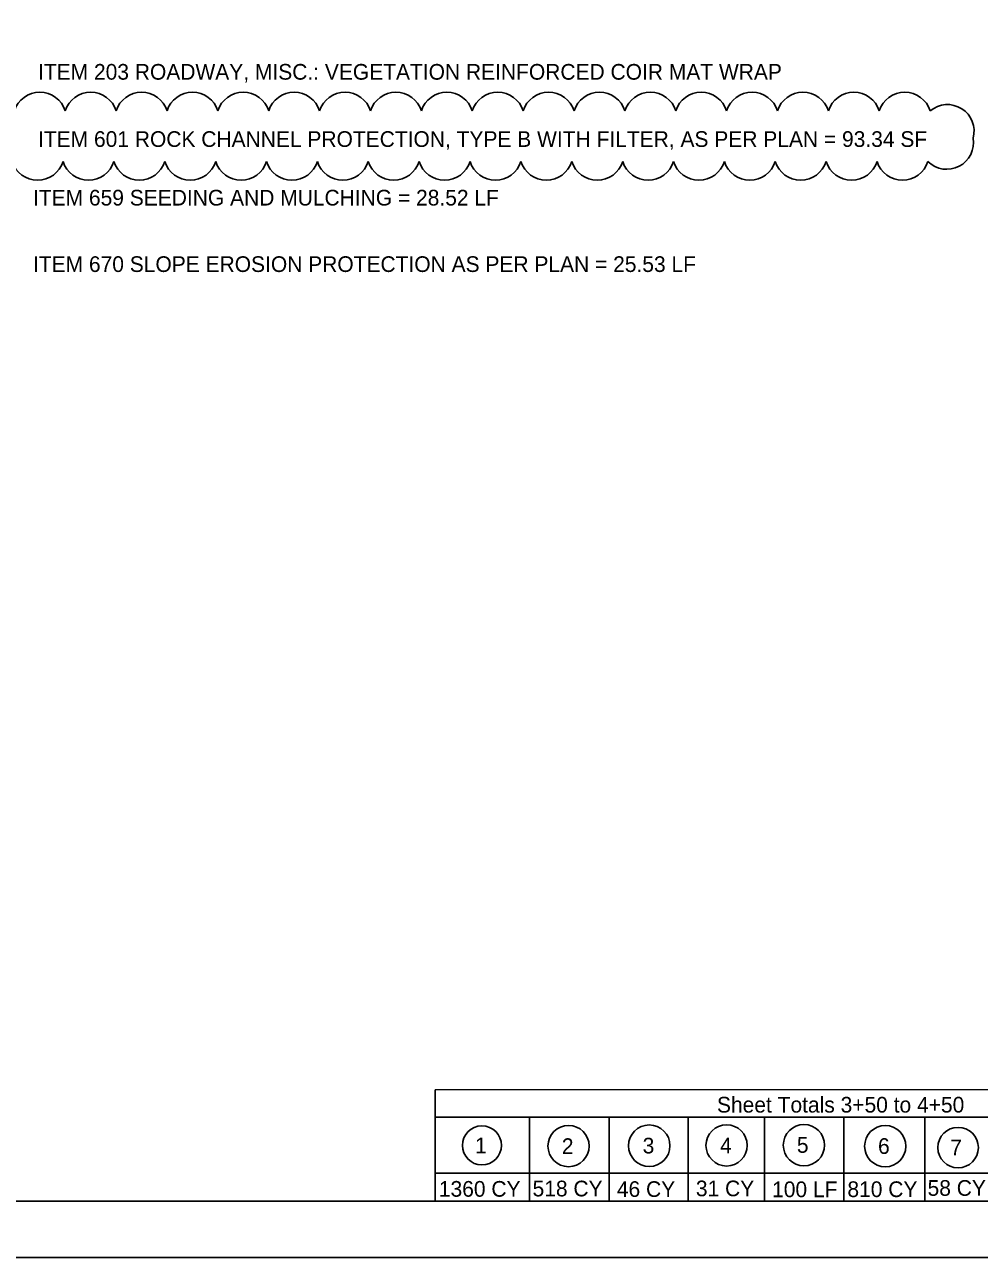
# Model space of a CAD drawing. Extents: x 0 to 34, y 0 to 22.
# Drawn here: x 21.21 to 29.73, y 0 to 11 of the extents above; entities that cross this region are included whole.
import ezdxf

# ---------------------------------------------------------------- set-up
doc = ezdxf.new("R2010")
doc.units = 0
for name, color, linetype in [('CS-ALGN-TEXT', 7, 'Continuous'), ('CS-ANNO', 7, 'Continuous'), ('CS-ANNO-MATC', 7, 'Continuous'), ('CS-ANNO-MATC-TEXT', 7, 'Continuous')]:
    doc.layers.add(name, color=color, linetype=linetype)

msp = doc.modelspace()

# ---------------------------------------------------------------- linework, layer by layer
at = {"layer": 'CS-ALGN-TEXT'}
for p, q in [((24.874, 1.496), (32, 1.5)), ((24.874, 0.496), (24.874, 1.496)), ((24.874, 1.25), (32, 1.25)), ((25.717, 0.496), (25.717, 1.246)), ((26.427, 0.496), (26.427, 1.246)), ((27.13, 0.496), (27.13, 1.246)), ((27.811, 0.496), (27.811, 1.246)), ((28.521, 0.496), (28.521, 1.246)), ((29.243, 0.496), (29.243, 1.246)), ((24.874, 0.75), (32, 0.75)), ((27.25, 0.5), (32, 0.5))]:
    msp.add_line(p, q, dxfattribs=at)
at = {"layer": 'CS-ANNO'}
msp.add_lwpolyline([(0, 0), (34, 0), (34, 22), (0, 22)], close=True, dxfattribs=at)
at = {"layer": 'CS-ANNO-MATC'}
msp.add_lwpolyline([(1.5, 21.5), (33.5, 21.5), (33.5, 0.5), (1.5, 0.5)], close=True, dxfattribs=at)
at = {"layer": 'CS-ANNO-MATC-TEXT'}
for centre, radius in [((25.291, 0.999), 0.174), ((26.064, 0.993), 0.184), ((26.784, 0.996), 0.185), ((27.474, 0.999), 0.184), ((28.164, 1.001), 0.184), ((28.889, 0.992), 0.184), ((29.539, 0.979), 0.181)]:
    msp.add_circle(centre, radius, dxfattribs=at)
for centre, start, end in [((21.347, 10.159), 17.5, 162.5), ((21.801, 10.159), 17.5, 162.5), ((22.255, 10.159), 17.5, 162.5), ((22.709, 10.159), 17.5, 162.5), ((23.162, 10.159), 17.5, 162.5), ((23.616, 10.159), 17.5, 162.5), ((24.07, 10.159), 17.5, 162.5), ((24.524, 10.159), 17.5, 162.5), ((24.978, 10.159), 17.5, 162.5), ((25.432, 10.159), 17.5, 162.5), ((25.886, 10.159), 17.5, 162.5), ((26.34, 10.159), 17.5, 162.5), ((26.794, 10.159), 17.5, 162.5), ((27.247, 10.159), 17.5, 162.5), ((27.701, 10.159), 17.5, 162.5), ((28.155, 10.159), 17.5, 162.5), ((28.609, 10.159), 17.5, 162.5), ((29.063, 10.159), 17.4564, 162.4564), ((29.444, 10.049), 345.1523, 130.1523), ((29.439, 9.947), 224.9312, 9.9312), ((21.327, 9.85), 197.5, 342.5), ((21.781, 9.85), 197.5, 342.5), ((22.235, 9.85), 197.5, 342.5), ((22.689, 9.85), 197.5, 342.5), ((23.143, 9.85), 197.5, 342.5), ((23.596, 9.85), 197.5, 342.5), ((24.05, 9.85), 197.5, 342.5), ((24.504, 9.85), 197.5, 342.5), ((24.958, 9.85), 197.5, 342.5), ((25.412, 9.85), 197.5, 342.5), ((25.866, 9.85), 197.5, 342.5), ((26.32, 9.85), 197.5, 342.5), ((26.774, 9.85), 197.5, 342.5), ((27.227, 9.85), 197.5, 342.5), ((27.681, 9.85), 197.5, 342.5), ((28.135, 9.85), 197.5, 342.5), ((28.589, 9.85), 197.5, 342.5), ((29.043, 9.85), 197.5, 342.5)]:
    msp.add_arc(centre, 0.238, start, end, dxfattribs=at)

# ---------------------------------------------------------------- texts
at = {"layer": 'CS-ALGN-TEXT'}
msp.add_text('Sheet Totals 3+50 to 4+50', height=0.14, dxfattribs=at).set_placement((27.388, 1.292))
at = {"layer": 'CS-ANNO-MATC-TEXT'}
for s, p in [('ITEM 203 ROADWAY, MISC.: VEGETATION REINFORCED COIR MAT WRAP', (21.331, 10.509)), ('ITEM 601 ROCK CHANNEL PROTECTION, TYPE B WITH FILTER, AS PER PLAN = 93.34 SF', (21.331, 9.909)), ('ITEM 659 SEEDING AND MULCHING = 28.52 LF', (21.286, 9.386)), ('ITEM 670 SLOPE EROSION PROTECTION AS PER PLAN = 25.53 LF', (21.286, 8.793)), ('1', (25.23, 0.929)), ('2', (26.004, 0.922)), ('3', (26.725, 0.927)), ('4', (27.416, 0.929)), ('5', (28.101, 0.933)), ('6', (28.825, 0.923)), ('7', (29.469, 0.91)), ('1360 CY', (24.907, 0.541)), ('518 CY', (25.743, 0.544)), ('46 CY', (26.495, 0.539)), ('31 CY', (27.2, 0.545)), ('100 LF', (27.88, 0.537)), ('810 CY', (28.552, 0.538)), ('58 CY', (29.267, 0.549))]:
    msp.add_text(s, height=0.14, dxfattribs=at).set_placement(p)

doc.saveas('drawing.dxf')
